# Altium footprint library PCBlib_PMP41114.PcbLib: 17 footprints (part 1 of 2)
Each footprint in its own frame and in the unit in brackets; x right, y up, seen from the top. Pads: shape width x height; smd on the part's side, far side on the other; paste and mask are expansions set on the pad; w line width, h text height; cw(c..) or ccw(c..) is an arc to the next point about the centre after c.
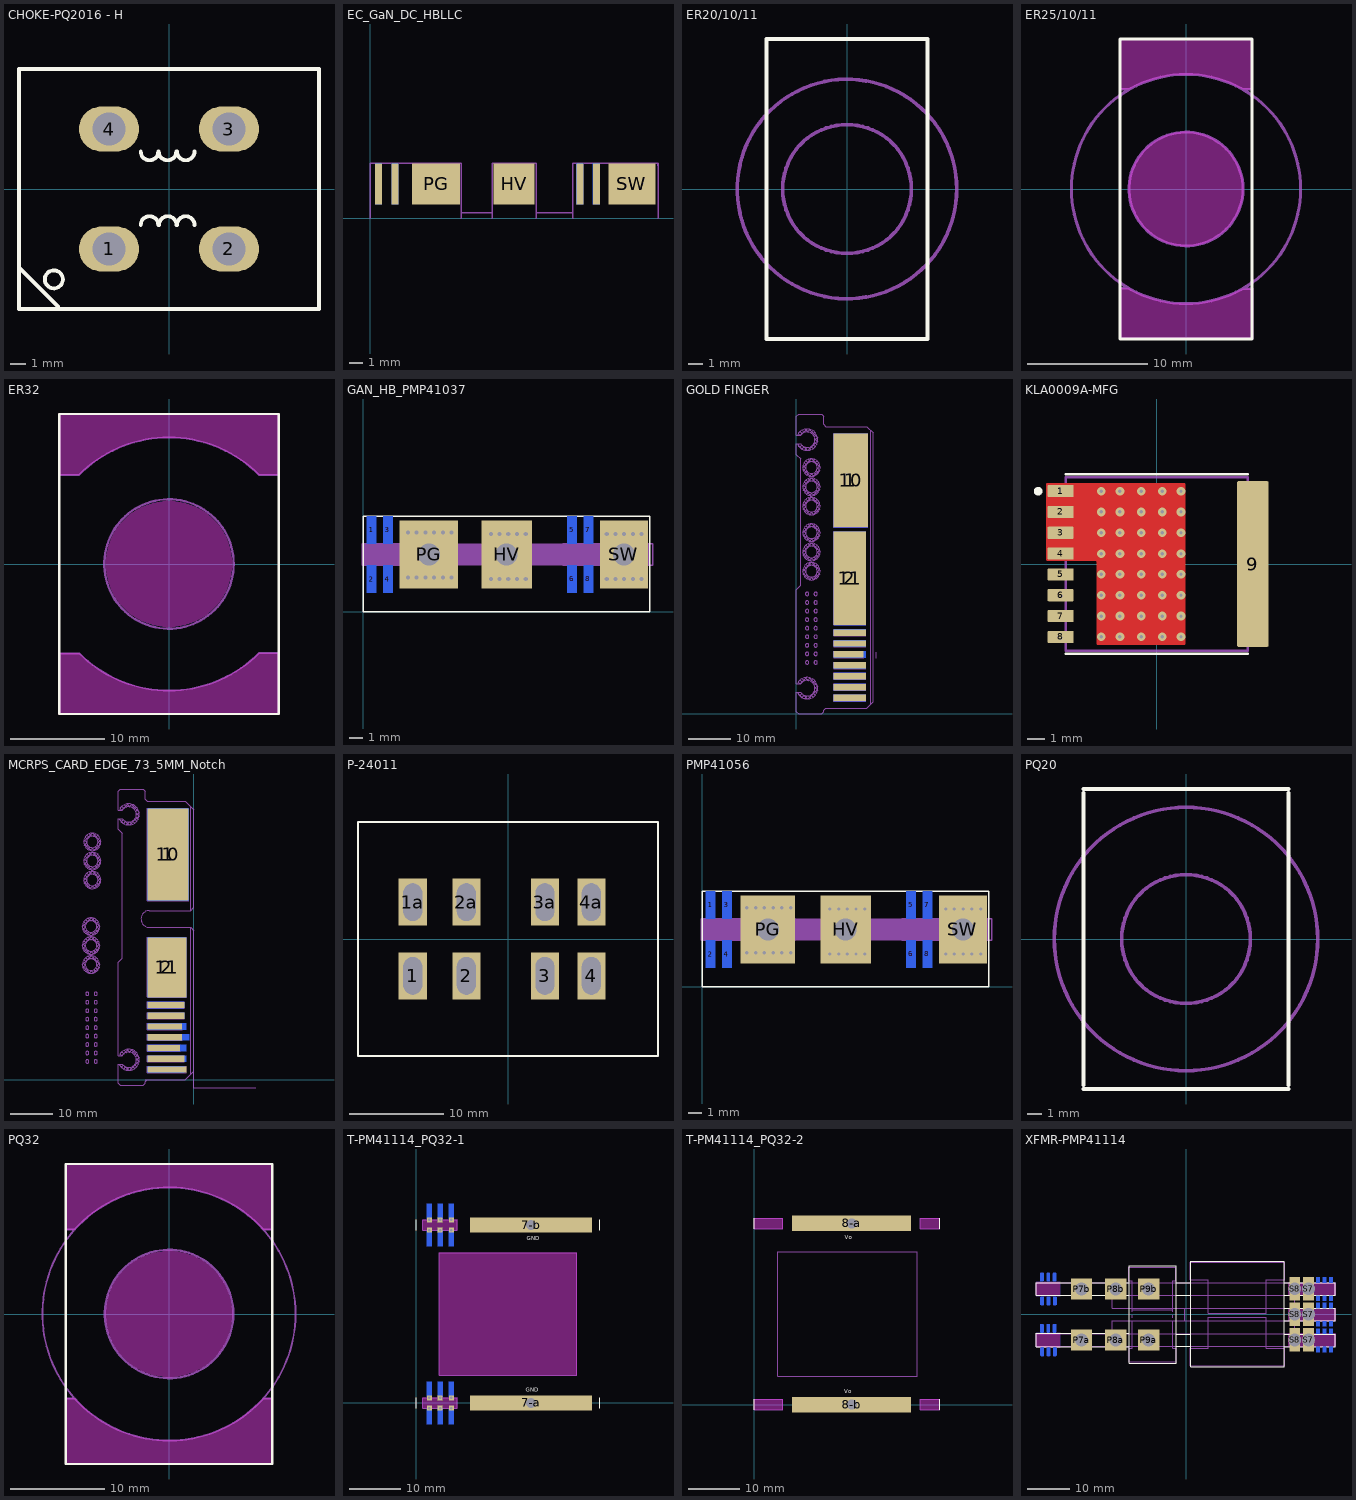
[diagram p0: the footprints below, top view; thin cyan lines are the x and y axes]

## CHOKE-PQ2016 - H [mm]
pads (4):
  oval 4x3 hole 2.2: 1(-4,-4) 2(4,-4) 3(4,4) 4(-4,4)
Top Overlay:
  circle w0.254: c-7.677,-6.026 r0.6
  lines w0.254: -10,-8 10,-8 ; -10,8 10,8 ; -9.906,-5.334 -7.406,-7.834 ; -1.883,-2.4 cw(c-1.3,-2.4) -0.717,-2.4 ; -1.883,2.5 ccw(c-1.3,2.5) -0.717,2.5 ; -0.683,2.5 ccw(c-0.1,2.5) 0.483,2.5 ; -0.666,-2.4 cw(c-0.083,-2.4) 0.5,-2.4 ; 0.534,-2.4 cw(c1.117,-2.4) 1.7,-2.4 ; 0.534,2.5 ccw(c1.117,2.5) 1.7,2.5
  lines w0.3: -10,-8 -10,8 ; 10,-8 10,8

## EC_GaN_DC_HBLLC [mm] "Edge connector of HB LLC GaN DC"
height 0.7
pads (11):
  rect 0.5x3 smd: 1(0.6,2.5) 3(1.8,2.5) 5(15.3,2.5) 7(16.5,2.5)
  rect 0.5x3 smd far side: 2(0.6,2.5) 4(1.8,2.5) 6(15.3,2.5) 8(16.5,2.5)
  rect 3x3 all layers, no hole: HV(10.5,2.5)
  rect 3.5x3 all layers, no hole: PG(4.8,2.5)
  rect 3.4x3 all layers, no hole: SW(19.1,2.5)
Mechanical 1:
  lines w0.1: -0.005,4 6.649,4 6.649,0.4 8.91,0.4 8.91,4 12.11,4 12.11,0.4 14.777,0.4 14.777,4 20.995,4 20.995,3.835
Mechanical 12:
  lines w0.1: 0,0 0,4 6.649,4 6.649,0 ; 8.9,0 8.9,4 12.1,4 12.1,0 ; 14.787,0 14.787,4 21,4 21,0

## ER20/10/11 [mm]
Top Overlay:
  lines w0.254: -5.5,-10.25 5.5,-10.25 5.5,10.25 -5.5,10.25 -5.5,-10.25
Mechanical 15:
  circle w0.254: c0,0 r4.4
  circle w0.254: c0,0 r7.5

## ER25/10/11 [mm] "Core"
Top Overlay:
  lines w0.254: -5.5,-12.5 -5.5,12.5 5.5,12.5 5.5,-12.5 -5.5,-12.5
Keep-Out Layer:
  board cut-out: -5.5,8.3 -4.714,8.3 -4.714,8.306 -4.352,8.501 -3.604,8.844 -2.83,9.121 -2.035,9.331 -1.224,9.471 -0.405,9.541 0.417,9.541 1.236,9.47 2.047,9.328 2.842,9.117 3.615,8.839 4.362,8.495 4.724,8.3 4.8,8.3 5.5,8.3 5.5,12.5 -5.5,12.5
  board cut-out: -5.493,-12.493 5.531,-12.493 5.531,-8.297 4.728,-8.297 4.363,-8.495 3.609,-8.842 2.828,-9.122 2.025,-9.333 1.207,-9.473 0.379,-9.542 -0.451,-9.539 -1.277,-9.464 -2.094,-9.317 -2.896,-9.1 -3.675,-8.815 -4.427,-8.462 -4.79,-8.262 -4.8,-8.278 -5.493,-8.278
  board cut-out: 0,-4.75 -0.311,-4.75 -0.929,-4.669 -1.53,-4.508 -2.105,-4.269 -2.645,-3.958 -3.139,-3.579 -3.579,-3.139 -3.958,-2.645 -4.269,-2.105 -4.508,-1.53 -4.669,-0.929 -4.75,-0.311 -4.75,0 -4.75,0.311 -4.669,0.929 -4.508,1.53 -4.269,2.105 -3.958,2.645 -3.579,3.139 -3.139,3.579 -2.645,3.958 -2.105,4.269 -1.53,4.508 -0.929,4.669 -0.311,4.75 0,4.75 0.311,4.75 0.929,4.669 1.53,4.508 2.105,4.269 2.645,3.958 3.139,3.579 3.579,3.139 3.958,2.645 4.269,2.105 4.508,1.53 4.669,0.929 4.75,0.311 4.75,0 4.75,-0.311 4.669,-0.929 4.508,-1.53 4.269,-2.105 3.958,-2.645 3.579,-3.139 3.139,-3.579 2.645,-3.958 2.105,-4.269 1.53,-4.508 0.929,-4.669 0.311,-4.75
Mechanical 2:
  circle w0.254: c0,0 r9.55
  circle w0.254: c0,0 r4.75
  lines w0.2: -5.5,-8.278 -4.8,-8.278 ; -5.493,-8.278 -5.493,-12.493 5.531,-12.493 5.531,-8.297 ; -4.79,-8.262 ccw(c0,0) 4.728,-8.297 5.5,-8.297 ; -4.714,8.3 -5.5,8.3 -5.5,12.5 5.5,12.5 5.5,8.3 4.8,8.3 ; -4.714,8.306 cw(c0,0) 4.724,8.3
3D body: height 0.25, standoff 0, extent -5.5,-12.5 5.5,12.5

## ER32 [mm] "Compatible to PQ32"
Top Overlay:
  lines w0.254: -11.7,-16 11.7,-16 11.7,16 -11.7,16 -11.7,-16
Keep-Out Layer:
  board cut-out: 0,-6.725 -0.33,-6.725 -0.988,-6.66 -1.636,-6.531 -2.268,-6.34 -2.879,-6.087 -3.462,-5.775 -4.011,-5.408 -4.522,-4.989 -4.989,-4.522 -5.408,-4.011 -5.775,-3.462 -6.087,-2.879 -6.34,-2.268 -6.531,-1.636 -6.66,-0.988 -6.725,-0.33 -6.725,0 -6.725,0.33 -6.66,0.988 -6.531,1.636 -6.34,2.268 -6.087,2.879 -5.775,3.462 -5.408,4.011 -4.989,4.522 -4.522,4.989 -4.011,5.408 -3.462,5.775 -2.879,6.087 -2.268,6.34 -1.636,6.531 -0.988,6.66 -0.33,6.725 0,6.725 0.33,6.725 0.988,6.66 1.636,6.531 2.268,6.34 2.879,6.087 3.462,5.775 4.011,5.408 4.522,4.989 4.989,4.522 5.408,4.011 5.775,3.462 6.087,2.879 6.34,2.268 6.531,1.636 6.66,0.988 6.725,0.33 6.725,0 6.725,-0.33 6.66,-0.988 6.531,-1.636 6.34,-2.268 6.087,-2.879 5.775,-3.462 5.408,-4.011 4.989,-4.522 4.522,-4.989 4.011,-5.408 3.462,-5.775 2.879,-6.087 2.268,-6.34 1.636,-6.531 0.988,-6.66 0.33,-6.725
  board cut-out: -11.7,9.5 -9.6,9.5 -9.596,9.496 -9.213,9.868 -8.405,10.564 -7.544,11.195 -6.636,11.756 -5.687,12.244 -4.702,12.655 -3.688,12.986 -2.651,13.237 -1.597,13.405 -0.534,13.489 0.534,13.489 1.597,13.405 2.651,13.237 3.688,12.986 4.702,12.655 5.687,12.244 6.636,11.756 7.544,11.195 8.405,10.564 9.213,9.868 9.596,9.496 9.6,9.5 11.7,9.5 11.7,16 -11.7,16
  board cut-out: -11.7,-16 -11.7,-9.542 -9.6,-9.542 -9.575,-9.517 -9.192,-9.888 -8.383,-10.582 -7.522,-11.21 -6.615,-11.768 -5.666,-12.253 -4.682,-12.662 -3.669,-12.992 -2.633,-13.241 -1.58,-13.407 -0.518,-13.49 0.548,-13.489 1.61,-13.404 2.662,-13.235 3.698,-12.984 4.71,-12.652 5.693,-12.241 6.641,-11.754 7.547,-11.193 8.407,-10.563 9.214,-9.867 9.596,-9.496 9.6,-9.5 11.7,-9.5 11.7,-16
Mechanical 2:
  circle w0.254: c0,0 r6.9
  lines w0.2: -9.6,-9.542 -11.7,-9.542 -11.7,-16 11.7,-16 11.7,-9.5 9.6,-9.5 ; -9.6,9.5 -11.7,9.5 -11.7,16 11.7,16 11.7,9.5 9.6,9.5 ; -9.596,9.496 cw(c0,0) 9.596,9.496 ; -9.575,-9.517 ccw(c0,0) 9.596,-9.496
3D body: height 0.25, standoff 0, extent -11.048,-15.968 11,16

## GAN_HB_PMP41037 [mm]
height 32
pads (11):
  rect 0.7x2 smd far side: 1(0.6,6) 2(0.6,2.4) 3(1.8,6) 4(1.8,2.4) 5(15.3,6) 6(15.3,2.4) 7(16.5,6) 8(16.5,2.4)
  rect 3.7x5 hole 1.6 square: HV(10.5,4.2)
  rect 4.3x5 hole 1.6 square: PG(4.8,4.2)
  rect 3.5x5 hole 1.6 square: SW(19.1,4.2)
via 3.9,2.5 diameter 0.5 hole 0.3
via 4.54,2.5 diameter 0.5 hole 0.3
via 5.18,2.5 diameter 0.5 hole 0.3
via 5.82,2.5 diameter 0.5 hole 0.3
via 6.46,2.5 diameter 0.5 hole 0.3
via 6.46,5.8 diameter 0.5 hole 0.3
via 5.82,5.8 diameter 0.5 hole 0.3
via 5.18,5.8 diameter 0.5 hole 0.3
via 4.54,5.8 diameter 0.5 hole 0.3
via 3.9,5.8 diameter 0.5 hole 0.3
via 9.34,2.4 diameter 0.5 hole 0.3
via 9.98,2.4 diameter 0.5 hole 0.3
via 10.62,2.4 diameter 0.5 hole 0.3
via 11.26,2.4 diameter 0.5 hole 0.3
via 11.9,2.4 diameter 0.5 hole 0.3
via 11.9,5.7 diameter 0.5 hole 0.3
via 11.26,5.7 diameter 0.5 hole 0.3
via 10.62,5.7 diameter 0.5 hole 0.3
via 9.98,5.7 diameter 0.5 hole 0.3
via 9.34,5.7 diameter 0.5 hole 0.3
via 17.84,2.4 diameter 0.5 hole 0.3
via 18.48,2.4 diameter 0.5 hole 0.3
via 19.12,2.4 diameter 0.5 hole 0.3
via 19.76,2.4 diameter 0.5 hole 0.3
via 20.4,2.4 diameter 0.5 hole 0.3
via 20.4,5.7 diameter 0.5 hole 0.3
via 19.76,5.7 diameter 0.5 hole 0.3
via 19.12,5.7 diameter 0.5 hole 0.3
via 18.48,5.7 diameter 0.5 hole 0.3
via 17.84,5.7 diameter 0.5 hole 0.3
via 3.26,5.8 diameter 0.5 hole 0.3
via 3.26,2.5 diameter 0.5 hole 0.3
Top Overlay:
  lines w0.1: 0,0 21,0 21,7 0,7 0,0
Mechanical 1:
  lines w0.1: -0.1,3.4 -0.1,5 6.8,5 6.8,3.4 -0.1,3.4 ; 8.763,3.4 12.246,3.4 12.246,5 8.763,5 8.763,3.4 ; 14.6,3.4 14.6,5 21.2,5 21.2,3.4 14.6,3.4
Mechanical 2:
  rectangle: 0,3.4 21,5
3D body: height 32, standoff 0, extent -0.1,3.4 21.2,5

## GOLD FINGER [mm]
pads (18):
  rect 8x21.83 smd: 1(12.748,54.51)
  rect 7.5x21.82 smd: 2(12.498,31.65)
  rect 7.5x1.5 smd: 3(12.498,18.96) 4(12.498,16.42) 6(12.498,11.34) 7(12.498,8.8) 8(12.498,6.26) 9(12.498,3.72)
  rect 7x1.5 smd: 5(12.248,13.88)
  rect 8x21.83 smd far side: 10(12.748,54.51)
  rect 7.5x21.82 smd far side: 11(12.498,31.65)
  rect 7.5x1.5 smd far side: 12(12.498,18.96) 13(12.498,16.42) 14(12.498,13.88) 15(12.498,11.34) 16(12.498,8.8) 17(12.498,6.26) 18(12.498,3.72)
Mechanical 16:
  drawing of 327 lines, arcs and shapes, not listed

## KLA0009A-MFG [mm]
height 16
pads (9):
  rrect14% 1.5x0.7 smd paste+0 mask-1000: 1(-5.539,4.2) 2(-5.539,3) 3(-5.539,1.8) 4(-5.539,0.6) 5(-5.539,-0.6) 6(-5.539,-1.8) 7(-5.539,-3) 8(-5.539,-4.2)
  rrect15% 1.843x9.6 smd paste-1000 mask-1000: 9(5.539,0)
via -3.208,4.2 diameter 0.5 hole 0.2
via -3.208,3 diameter 0.5 hole 0.2
via -3.208,1.8 diameter 0.5 hole 0.2
via -3.208,0.6 diameter 0.5 hole 0.2
via -3.208,-0.6 diameter 0.5 hole 0.2
via -3.208,-1.8 diameter 0.5 hole 0.2
via -3.208,-3 diameter 0.5 hole 0.2
via -3.208,-4.2 diameter 0.5 hole 0.2
via -2.12,4.2 diameter 0.5 hole 0.2
via -2.12,3 diameter 0.5 hole 0.2
via -2.12,1.8 diameter 0.5 hole 0.2
via -2.12,0.6 diameter 0.5 hole 0.2
via -2.12,-0.6 diameter 0.5 hole 0.2
via -2.12,-1.8 diameter 0.5 hole 0.2
via -2.12,-3 diameter 0.5 hole 0.2
via -2.12,-4.2 diameter 0.5 hole 0.2
via -0.9,4.2 diameter 0.5 hole 0.2
via -0.9,3 diameter 0.5 hole 0.2
via -0.9,1.8 diameter 0.5 hole 0.2
via -0.9,0.6 diameter 0.5 hole 0.2
via -0.9,-0.6 diameter 0.5 hole 0.2
via -0.9,-1.8 diameter 0.5 hole 0.2
via -0.9,-3 diameter 0.5 hole 0.2
via -0.9,-4.2 diameter 0.5 hole 0.2
via 0.32,4.2 diameter 0.5 hole 0.2
via 0.32,3 diameter 0.5 hole 0.2
via 0.32,1.8 diameter 0.5 hole 0.2
via 0.32,0.6 diameter 0.5 hole 0.2
via 0.32,-0.6 diameter 0.5 hole 0.2
via 0.32,-1.8 diameter 0.5 hole 0.2
via 0.32,-3 diameter 0.5 hole 0.2
via 0.32,-4.2 diameter 0.5 hole 0.2
via 1.4,4.2 diameter 0.5 hole 0.2
via 1.4,3 diameter 0.5 hole 0.2
via 1.4,1.8 diameter 0.5 hole 0.2
via 1.4,0.6 diameter 0.5 hole 0.2
via 1.4,-0.6 diameter 0.5 hole 0.2
via 1.4,-1.8 diameter 0.5 hole 0.2
via 1.4,-3 diameter 0.5 hole 0.2
via 1.4,-4.2 diameter 0.5 hole 0.2
Top Layer:
  region: -6.36,4.6 -6.36,4.614 -6.349,4.64 -6.33,4.659 -6.304,4.67 -6.29,4.67 1.587,4.67 1.601,4.67 1.627,4.659 1.646,4.64 1.657,4.614 1.657,4.6 1.657,-4.6 1.657,-4.614 1.646,-4.64 1.627,-4.659 1.601,-4.67 1.587,-4.67 -3.388,-4.67 -3.402,-4.67 -3.428,-4.659 -3.447,-4.64 -3.458,-4.614 -3.458,-4.6 -3.458,0.13 -3.459,0.14 -3.466,0.158 -3.48,0.172 -3.498,0.179 -3.508,0.18 -6.29,0.18 -6.304,0.18 -6.33,0.191 -6.349,0.21 -6.36,0.236 -6.36,0.25
Top Overlay:
  circle w0.25: c-6.837,4.197 r0.125
  lines w0.15: -5.24,-5.175 5.24,-5.175 ; -5.24,5.175 5.24,5.175
Top Paste:
  drawing of 40 lines, arcs and shapes, not listed
Top Solder:
  drawing of 6 lines, arcs and shapes, not listed
Mechanical 5:
  lines w0.15: -5.24,-5 -5.24,5 5.24,5 5.24,-5 -5.24,-5
  text ".Designator" at 0.733,-0.083 h0.5
3D body "IC_LMG365x_TO-9.STEP": height 0.25, standoff 0, extent -6.46,-5.1 6.56,5.1

## MCRPS_CARD_EDGE_73_5MM_Notch [mm] "Edge Connector with golden finger"
pads (18):
  rect 9.75x21.83 smd: 1(-6.1,53.2)
  rect 9.25x14.2 smd: 2(-6.369,26.52)
  rect 8.75x1.5 smd: 3(-6.625,17.63) 4(-6.625,15.09) 8(-6.625,4.93)
  rect 8.25x1.5 smd: 5(-6.875,12.55) 6(-6.875,10.01)
  rect 7.75x1.5 smd: 7(-7.125,7.47)
  rect 9.25x1.5 smd: 9(-6.375,2.39)
  rect 9.75x21.83 smd far side: 10(-6.125,53.19)
  rect 9.25x14.2 smd far side: 11(-6.375,26.52)
  rect 8.75x1.5 smd far side: 12(-6.625,17.63) 13(-6.625,15.09) 18(-6.625,2.39)
  rect 9.25x1.5 smd far side: 14(-6.375,12.55) 16(-6.375,7.47) 17(-6.375,4.93)
  rect 9.9x1.5 smd far side: 15(-6.05,10.01)
Mechanical 10:
  lines w0.025: 0,2 0,-1.9 14.6,-1.9
  text "30u in GOLD  /100u in NICKEL" at 1.648,16.052 h0.76
  text "2x 0.77mm, 2x 30 deg" at 1.452,-1.494 h0.76
Mechanical 15:
  drawing of 329 lines, arcs and shapes, not listed
Mechanical 16:
  drawing of 325 lines, arcs and shapes, not listed

## P-24011 [mm] "LLC transformer from Cyntec"
pads (8):
  rect 3x5 hole 2 slot 4 at 90 deg: 1(-10.16,-3.937) 1a(-10.16,3.937) 2(-4.445,-3.937) 2a(-4.445,3.937) 3(3.937,-3.937) 3a(3.937,3.937) 4(8.89,-3.937) 4a(8.89,3.937)
Top Overlay:
  lines w0.2: -16,-12.5 -16,12.5 16,12.5 16,-12.5 -16,-12.5

## PMP41056 [mm] "GaN board Interface"
height 32
pads (11):
  rect 0.7x2 smd far side: 1(0.6,6) 2(0.6,2.4) 3(1.8,6) 4(1.8,2.4) 5(15.3,6) 6(15.3,2.4) 7(16.5,6) 8(16.5,2.4)
  rect 3.7x5 hole 1.6 square: HV(10.5,4.2)
  rect 4x5 hole 1.6 square: PG(4.8,4.2)
  rect 3.5x5 hole 1.6 square: SW(19.1,4.2)
via 3.26,2.5 diameter 0.5 hole 0.254
via 3.26,5.8 diameter 0.5 hole 0.254
via 17.84,5.7 diameter 0.5 hole 0.254
via 18.48,5.7 diameter 0.5 hole 0.254
via 19.12,5.7 diameter 0.5 hole 0.254
via 19.76,5.7 diameter 0.5 hole 0.254
via 20.4,5.7 diameter 0.5 hole 0.254
via 20.4,2.4 diameter 0.5 hole 0.254
via 19.76,2.4 diameter 0.5 hole 0.254
via 19.12,2.4 diameter 0.5 hole 0.254
via 18.48,2.4 diameter 0.5 hole 0.254
via 17.84,2.4 diameter 0.5 hole 0.254
via 9.34,5.7 diameter 0.5 hole 0.254
via 9.98,5.7 diameter 0.5 hole 0.254
via 10.62,5.7 diameter 0.5 hole 0.254
via 11.26,5.7 diameter 0.5 hole 0.254
via 11.9,5.7 diameter 0.5 hole 0.254
via 11.9,2.4 diameter 0.5 hole 0.254
via 11.26,2.4 diameter 0.5 hole 0.254
via 10.62,2.4 diameter 0.5 hole 0.254
via 9.98,2.4 diameter 0.5 hole 0.254
via 9.34,2.4 diameter 0.5 hole 0.254
via 3.9,5.8 diameter 0.5 hole 0.254
via 4.54,5.8 diameter 0.5 hole 0.254
via 5.18,5.8 diameter 0.5 hole 0.254
via 5.82,5.8 diameter 0.5 hole 0.254
via 6.46,5.8 diameter 0.5 hole 0.254
via 6.46,2.5 diameter 0.5 hole 0.254
via 5.82,2.5 diameter 0.5 hole 0.254
via 5.18,2.5 diameter 0.5 hole 0.254
via 4.54,2.5 diameter 0.5 hole 0.254
via 3.9,2.5 diameter 0.5 hole 0.254
Top Overlay:
  lines w0.1: 0,0 0,7 21,7 21,0 0,0
Mechanical 1:
  lines w0.1: -0.1,3.4 6.8,3.4 6.8,5 -0.1,5 -0.1,3.4 ; 8.763,3.4 8.763,5 12.246,5 12.246,3.4 8.763,3.4 ; 14.6,3.4 21.2,3.4 21.2,5 14.6,5 14.6,3.4
Mechanical 2:
  rectangle: 0,3.4 21,5

## PQ20 [mm] "Core"
Top Overlay:
  lines w0.254: -7,-10.25 7,-10.25 ; -7,-10 -7,10 ; -7,10.25 7,10.25 ; 7,-10 7,10
Mechanical 2:
  circle w0.254: c0,0 r4.4
  circle w0.254: c0,0 r9

## PQ32 [mm] "Core"
Top Overlay:
  lines w0.254: -11,-16 11,-16 11,16 -11,16 -11,-16
Keep-Out Layer:
  board cut-out: 0,-6.725 -0.33,-6.725 -0.988,-6.66 -1.636,-6.531 -2.268,-6.34 -2.879,-6.087 -3.462,-5.775 -4.011,-5.408 -4.522,-4.989 -4.989,-4.522 -5.408,-4.011 -5.775,-3.462 -6.087,-2.879 -6.34,-2.268 -6.531,-1.636 -6.66,-0.988 -6.725,-0.33 -6.725,0 -6.725,0.33 -6.66,0.988 -6.531,1.636 -6.34,2.268 -6.087,2.879 -5.775,3.462 -5.408,4.011 -4.989,4.522 -4.522,4.989 -4.011,5.408 -3.462,5.775 -2.879,6.087 -2.268,6.34 -1.636,6.531 -0.988,6.66 -0.33,6.725 0,6.725 0.33,6.725 0.988,6.66 1.636,6.531 2.268,6.34 2.879,6.087 3.462,5.775 4.011,5.408 4.522,4.989 4.989,4.522 5.408,4.011 5.775,3.462 6.087,2.879 6.34,2.268 6.531,1.636 6.66,0.988 6.725,0.33 6.725,0 6.725,-0.33 6.66,-0.988 6.531,-1.636 6.34,-2.268 6.087,-2.879 5.775,-3.462 5.408,-4.011 4.989,-4.522 4.522,-4.989 4.011,-5.408 3.462,-5.775 2.879,-6.087 2.268,-6.34 1.636,-6.531 0.988,-6.66 0.33,-6.725
  board cut-out: -11,-16 -11,-9 -10.062,-9 -9.676,-9.415 -8.851,-10.193 -7.965,-10.9 -7.022,-11.53 -6.03,-12.079 -4.995,-12.542 -3.925,-12.917 -2.827,-13.201 -1.71,-13.391 -0.58,-13.488 0.554,-13.489 1.684,-13.395 2.802,-13.206 3.9,-12.924 4.971,-12.552 6.006,-12.09 7,-11.544 7.943,-10.916 8.831,-10.211 9.657,-9.434 10.045,-9.02 10.045,-9 11,-9 11,-16
  board cut-out: -11,9 -11,16 11,16 11,9 10.045,9 10.062,9 9.676,9.415 8.851,10.193 7.965,10.9 7.022,11.53 6.03,12.079 4.995,12.542 3.925,12.917 2.827,13.201 1.71,13.391 0.58,13.488 -0.554,13.489 -1.684,13.395 -2.802,13.206 -3.9,12.924 -4.971,12.552 -6.006,12.09 -7,11.544 -7.943,10.916 -8.831,10.211 -9.657,9.434 -10.045,9.02 -10.045,9
Mechanical 2:
  circle w0.2: c0,0 r13.5
  circle w0.254: c0,0 r6.85
  lines w0.2: -10.045,9 -11,9 -11,16 11,16 11,9 10.045,9 ; -10.045,9.02 cw(c0,0) 10.062,9 ; 10.045,-9.02 cw(c0,0) -10.062,-9 -11,-9 -11,-16 11,-16 11,-9 10.045,-9
3D body: height 0.25, standoff 0, extent -11.048,-15.968 11,16

## T-PM41114_PQ32-1 [mm] "Customized to Sunlord"
pads (26):
  rect 1x3 smd far side: 1-a(2.545,-2.7) 1-b(2.545,32.3) 2-a(4.65,-2.7) 2-b(4.65,32.3) 3-a(6.85,-2.7) 3-b(6.85,32.3) 4-a(2.545,2.7) 4-b(2.545,37.7) 5-a(4.65,2.7) 5-b(4.65,37.7) 6-a(6.85,2.7) 6-b(6.85,37.7)
  rect 1x1 hole 0.5: 1-a(2.545,-1) 1-b(2.545,34) 2-a(4.65,-1) 2-b(4.65,34) 3-a(6.85,-1) 3-b(6.85,34) 4-a(2.545,1) 4-b(2.545,36) 5-a(4.65,1) 5-b(4.65,36) 6-a(6.85,1) 6-b(6.85,36)
  rect 24x3 hole 2 square: 7-a(22.55,0) 7-b(22.55,35)
Top Overlay:
  lines w0.2: 0,-1 0,1 ; 0,34 0,36 ; 36,-1 36,1 ; 36,34 36,36
  text "GND" at 21.452,2.252 h0.76
  text "GND" at 21.652,32.052 h0.76
Keep-Out Layer:
  board cut-out: 4.5,5.5 4.5,29.5 31.5,29.5 31.5,5.5
  board cut-out: 1.2,-1 8,-1 8,1 1.2,1
  board cut-out: 1.2,34 8,34 8,36 1.2,36
Mechanical 1:
  lines w0.2: 1.2,-1 1.2,1 ; 1.2,-1 8,-1 ; 1.2,-1 1.2,1 ; 1.2,-1 8,-1 ; 1.2,1 8,1 ; 1.2,1 8,1 ; 8,-1 8,1 ; 8,-1 8,1 ; 1.2,34 1.2,36 8,36 8,34 1.2,34 ; 4.5,5.5 4.5,29.5 31.5,29.5 31.5,5.5 4.5,5.5
3D body: height 27.5, standoff -4.5, extent 4.5,5.5 31.5,29.5
3D body: height 30, standoff 0, extent 0,34 36,36
3D body: height 30, standoff 0, extent 0,-1 36,1

## T-PM41114_PQ32-2 [mm]
pads (2):
  rect 23x3 hole 2 square: 8-a(18.8,35) 8-b(18.8,0)
Top Overlay:
  lines w0.2: 0,-1 0,1 ; 0,34 0,36 ; 35.8,-1 35.8,1 ; 35.8,34 35.8,36
  text "Vo" at 17.352,2.152 h0.76
  text "Vo" at 17.452,31.952 h0.76
Keep-Out Layer:
  board cut-out: 0,-1 5.5,-1 5.5,1 0,1
  board cut-out: 0,34 5.5,34 5.5,36 0,36
  board cut-out: 35.8,36 32.1,36 32.1,34 35.8,34
  board cut-out: 35.8,1 32.1,1 32.1,-1 35.8,-1
Mechanical 1:
  lines w0.2: 0,-1 0,1 5.5,1 5.5,-1 0,-1 ; 0,34 0,36 5.5,36 5.5,34 0,34 ; 4.5,5.5 4.5,29.5 31.5,29.5 31.5,5.5 4.5,5.5 ; 32.1,-1 35.8,-1 35.8,1 32.1,1 32.1,-1 ; 32.1,34 35.8,34 35.8,36 32.1,36 32.1,34
3D body: height 32, standoff 0, extent 4.5,5.5 31.5,29.5
3D body: height 30, standoff 0, extent 0,34 35.8,36
3D body: height 30, standoff 0, extent 0,-1 35.8,1

## XFMR-PMP41114 [mm]
pads (42):
  rrect50% 0.8x2 smd far side: P1a(-33.874,-8.75) P1b(-33.874,3.21) P2a(-33.925,-3.25) P2b(-33.925,8.75) P3a(-32.374,-8.75) P3b(-32.374,3.21) P4a(-32.425,-3.25) P4b(-32.425,8.75) P5a(-30.874,-8.75) P5b(-30.874,3.21) P6a(-30.925,-3.25) P6b(-30.925,8.75)
  rect 5x5 hole 3 square: P7a(-24.623,-6.001) P7b(-24.622,5.999) P8a(-16.605,-6.001) P8b(-16.605,5.999) P9a(-8.876,-6.001) P9b(-8.875,5.999)
  rect 0.8x1.2 smd far side: S1(33.925,-8.212) S1(33.925,-2.201) S1(33.925,3.799) S2(33.925,-3.912) S2(33.925,2.099) S2(33.925,8.099) S3(32.425,-8.212) S3(32.425,-2.201) S3(32.425,3.799) S4(32.425,-3.912) S4(32.425,2.099) S4(32.425,8.099) S5(30.925,-8.212) S5(30.925,-2.201) S5(30.925,3.799) S6(30.925,-3.912) S6(30.925,2.099) S6(30.925,8.099)
  rect 2.5x5.5 hole 3 square: S7(28.654,-5.962) S7(28.654,0.049) S7(28.654,6.049) S8(25.414,-5.962) S8(25.414,0.049) S8(25.414,6.049)
Top Overlay:
  lines w0.2: -13.533,4.489 -35.273,4.489 -35.273,7.489 -13.433,7.489 ; -13.523,-4.392 -35.307,-4.392 -35.307,-7.601 -13.423,-7.601 ; -2.423,-7.501 0.977,-7.501 ; -2.423,-4.601 0.977,-4.601 0.977,-1.601 ; -2.423,4.499 0.977,4.499 ; -2.423,7.499 0.977,7.499 ; 0.977,-1.501 0.977,1.499 ; 22.977,-4.601 34.877,-4.601 34.877,-7.601 23.077,-7.601 ; 22.977,1.499 34.877,1.499 34.877,-1.501 23.077,-1.501 ; 22.988,4.489 34.911,4.489 34.911,7.489 22.988,7.489
  lines w0.254: -13.423,-11.401 -2.423,-11.401 -2.423,11.39 -13.423,11.39 -13.423,-11.401 ; 0.977,-12.278 22.977,-12.278 22.977,12.499 0.977,12.499 0.977,-12.278
Keep-Out Layer:
  board cut-out: 23.961,4.499 23.961,7.499 35.111,7.499 35.111,4.499
  board cut-out: 23.961,-1.501 23.961,1.499 35.111,1.499 35.111,-1.501
  board cut-out: -35.289,4.299 -35.289,7.699 -29.639,7.699 -29.639,4.299
  board cut-out: 23.961,-7.511 23.961,-4.511 35.111,-4.511 35.111,-7.511
  board cut-out: -35.289,-7.701 -35.289,-4.301 -29.639,-4.301 -29.639,-7.701
Mechanical 2:
  lines w0.2: -35.289,-7.511 -35.289,-4.511 ; -35.289,-7.511 34.911,-7.511 34.911,-4.511 -35.289,-4.511 ; -35.289,7.488 -35.289,4.488 34.911,4.488 34.911,7.499 -35.289,7.499 ; -17.456,-4.511 -17.456,-1.512 25.431,-1.512 ; -17.456,4.489 -17.456,1.499 34.911,1.499 34.911,-1.501 -0.373,-1.501 -0.373,1.488 25.431,1.488 ; -4.373,-4.511 25.431,-4.511 ; 25.431,-4.501 25.431,-1.501 ; 25.431,1.499 25.431,4.499
Mechanical 15:
  lines w0.254: -13.484,-7.901 -12.734,-7.901 -12.734,-1.424 ; -13.424,-7.898 -13.424,-11.098 -2.424,-11.098 -2.424,-7.898 ; -12.734,-1.924 -12.734,-1.424 ; -12.734,-0.761 -12.734,-0.174 ; -12.734,0.658 -12.734,1.076 ; -3.234,-1.924 -3.234,-1.424 ; -3.234,-0.761 -3.234,-0.174 ; -3.234,0.658 -3.234,1.076 ; -2.484,-7.901 -3.234,-7.901 -3.234,-1.424 ; 23.027,-12.001 0.877,-12.001 0.877,-7.901 5.152,-7.901 5.152,-0.674 18.752,-0.674 18.752,-7.901 23.027,-7.901 23.027,-11.924 ; -12.734,-1.424 -3.234,-1.424 ; -12.734,1.076 -3.234,1.076 ; -12.734,1.076 -12.734,7.899 -13.484,7.899 -13.484,11.099 -2.484,11.099 -2.484,7.899 -3.234,7.899 -3.234,1.076 ; 0.877,8.099 5.152,8.099 5.152,0.326 18.752,0.326 18.752,8.099 23.027,8.099 23.027,12.199 0.877,12.199 0.877,8.099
